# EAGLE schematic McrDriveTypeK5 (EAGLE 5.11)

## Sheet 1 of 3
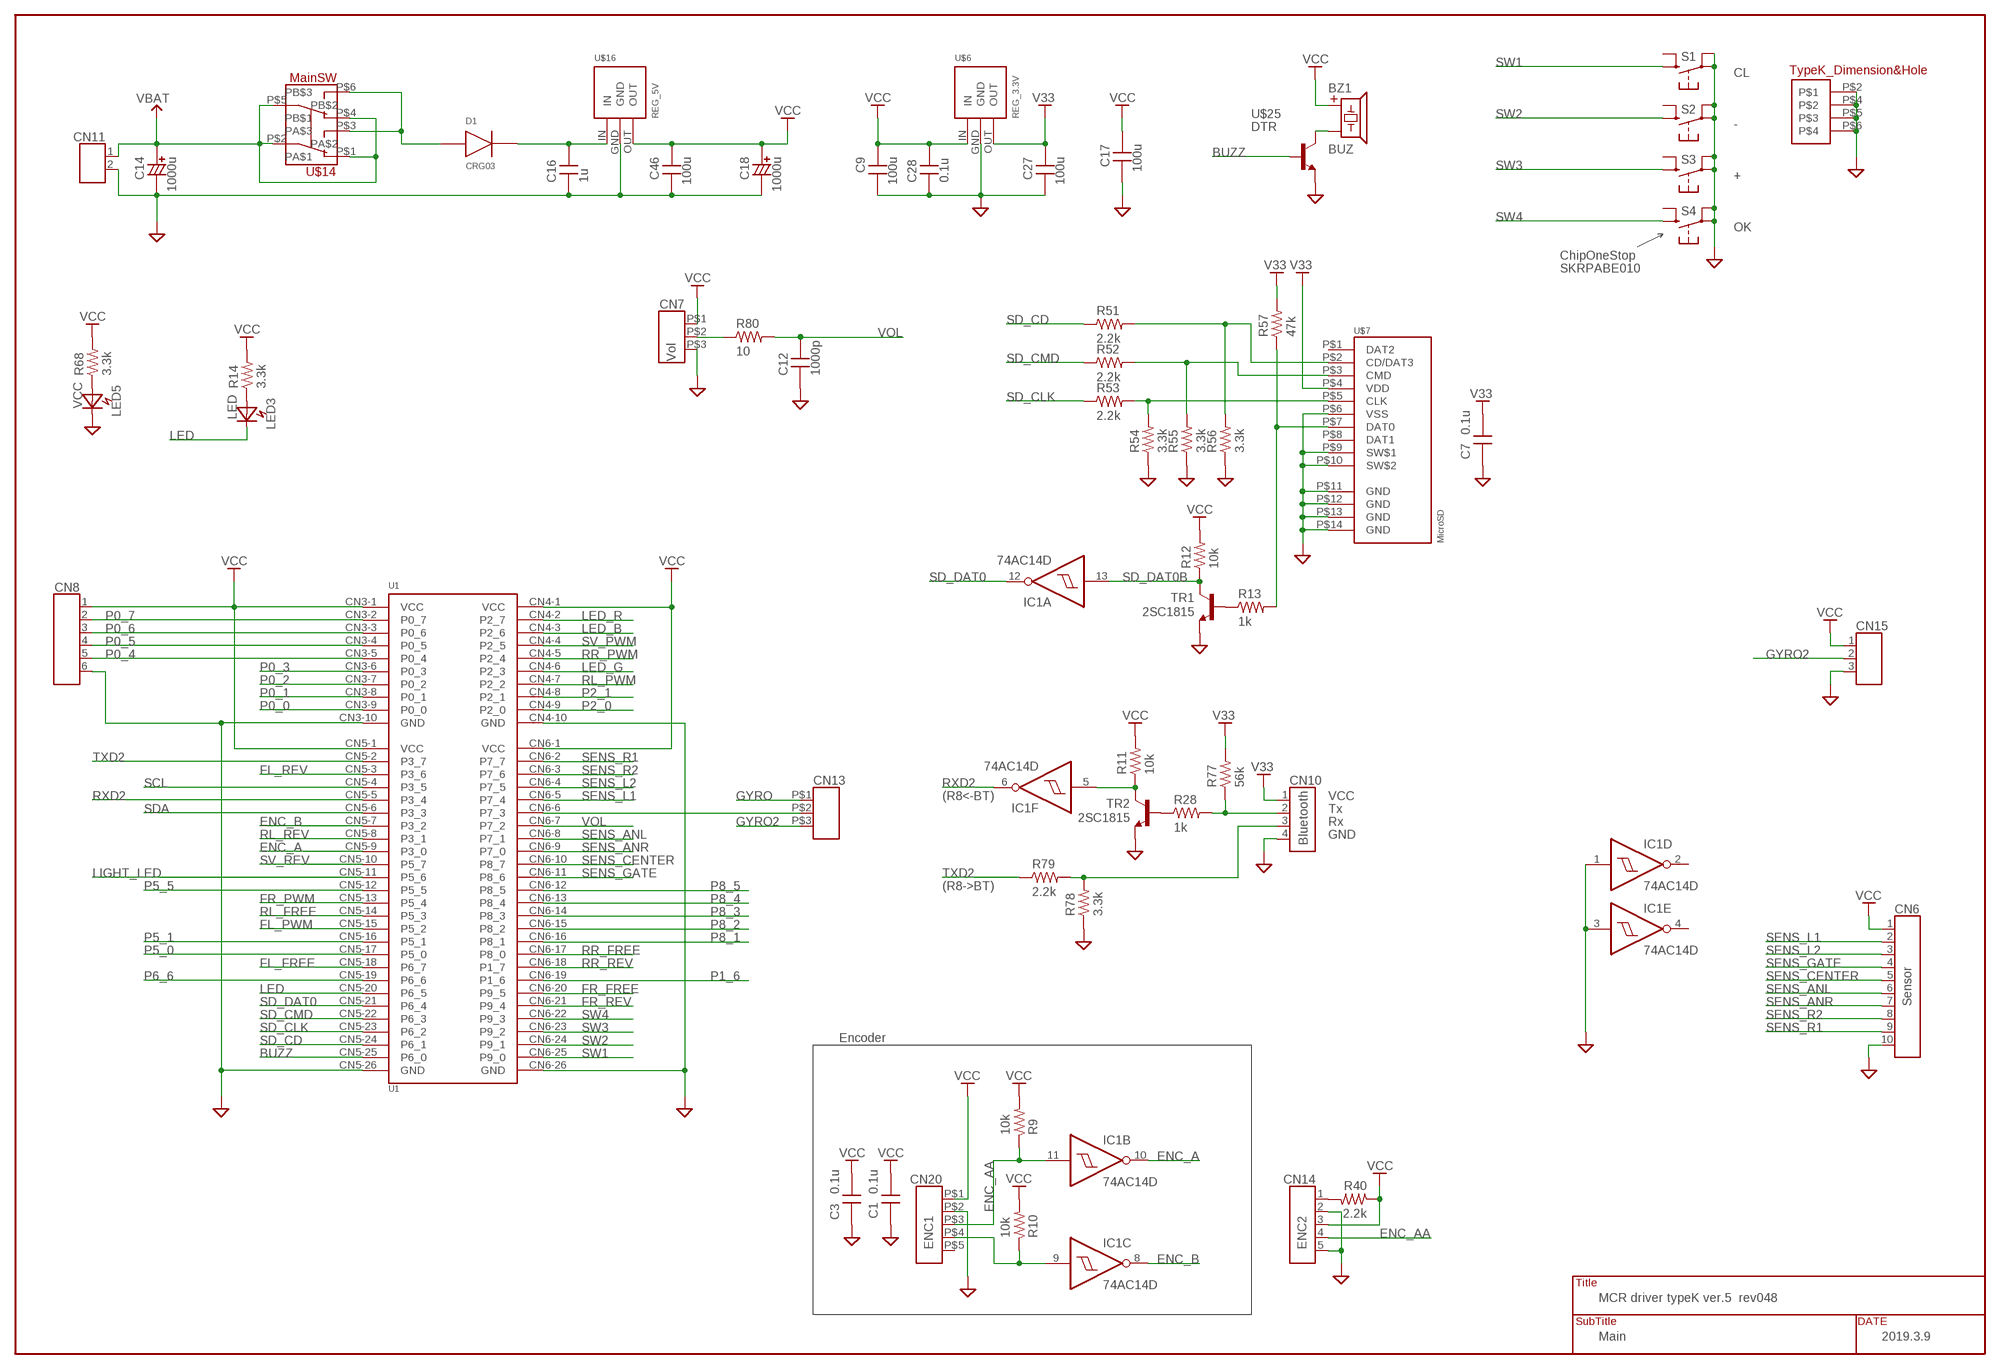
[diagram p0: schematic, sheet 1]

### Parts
BZ1  BUZ  BZ-13  [13B]
C1  0.1u  CAPSM1608C  [C1608C]
C3  0.1u  CAPSM1608C  [C1608C]
C7  0.1u  CAPSM1608C  [C1608C]
C9  100u  CAPSM3216  [C3216]
C12  1000p  CAPSM1608C  [C1608C]
C14  1000u  CCAP10.5  [CCAP_10.5]
C16  1u  CAPSM1608C  [C1608C]
C17  100u  CAPSM3216  [C3216]
C18  1000u  CCAP10.5  [CCAP_10.5]
C27  100u  CAPSM3216  [C3216]
C28  0.1u  CAPSM1608C  [C1608C]
C46  100u  CAPSM3216  [C3216]
CN6  Sensor  CON_10P-1.0  [ML10]
CN7  Vol  CON_3P-XH  [3P-XH]
CN8  CON_6P-1.0B  [6P-S2]
CN10  Bluetooth  CON_4P-1.0-2  [4P-S2]
CN11  CON_2P-VH  [2P-VH]
CN13  CON_3P-SMD  [3P-SMD]
CN14  ENC2  CON_5P-1.0B  [5P-S2]
CN15  CON_3P-1.0-2  [3P-S2]
CN20  ENC1  CON_5P-DF3A  [DF3A-5P]
D1  CRG03  DIODES  [CRG03]
IC1  74AC14D  [SO14]
LED3  LED  LED-1608B  [LED_1608B]
LED5  VCC  LED-1608B  [LED_1608B]
R9  10k  R1608C  [C1608C]
R10  10k  R1608C  [C1608C]
R11  10k  R1608C  [C1608C]
R12  10k  R1608C  [C1608C]
R13  1k  R1608C  [C1608C]
R14  3.3k  R1608C  [C1608C]
R28  1k  R1608C  [C1608C]
R40  2.2k  R1608C  [C1608C]
R51  2.2k  R1608C  [C1608C]
R52  2.2k  R1608C  [C1608C]
R53  2.2k  R1608C  [C1608C]
R54  3.3k  R1608C  [C1608C]
R55  3.3k  R1608C  [C1608C]
R56  3.3k  R1608C  [C1608C]
R57  47k  R1608C  [C1608C]
R68  3.3k  R1608C  [C1608C]
R77  56k  R1608C  [C1608C]
R78  3.3k  R1608C  [C1608C]
R79  2.2k  R1608C  [C1608C]
R80  10  R1608C  [C1608C]
S1  CL  T-SWITCHSKRP  [TSW_SKRP]
S2  -  T-SWITCHSKRP  [TSW_SKRP]
S3  +  T-SWITCHSKRP  [TSW_SKRP]
S4  OK  T-SWITCHSKRP  [TSW_SKRP]
TR1  2SC1815  2SC1815-SC70  [SC70]
TR2  2SC1815  2SC1815-SC70  [SC70]
U1  RY-R8C38  [RY-R8C38]
U$1  TYPE_K5EE  [TYPE_K5E]
U$6  REG_3.3V  REGULATOR-SMD  [NJM2391DL1]
U$7  MicroSD  SD-MICRO  [DM3AT-SF-PEJ]
U$14  MainSW  SW-6P-0.9  [SW-6P-2.5X3.3]
U$16  REG_5V  REGULATOR-SMD  [NJM2391DL1]
U$25  DTR  2SC1815-SC70  [SC70]

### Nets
BUZZ: U1.CN5-25(P6_0) U$25.B
ENC_A: IC1.10(B:O) U1.CN5-9(P3_0)
ENC_AA: CN14.4 CN20.P$3 IC1.11(B:I) R9.1
ENC_B: IC1.8(C:O) U1.CN5-7(P3_2)
FL_FREE: U1.CN5-18(P6_7) ; also sheet 2
FL_PWM: U1.CN5-15(P5_2) ; also sheet 2
FL_REV: U1.CN5-3(P3_6) ; also sheet 2
FR_FREE: U1.CN6-20(P9_5) ; also sheet 2
FR_PWM: U1.CN5-13(P5_4) ; also sheet 2
FR_REV: U1.CN6-21(P9_4) ; also sheet 2
GND: C1.1 C3.1 C7.1 C9.2 C12.1 C14.- C16.1 C17.2 C18.- C27.2 C28.1 C46.2 CN6.10 CN7.P$3 CN8.6 CN10.4 CN11.2 CN14.2 CN14.5 CN15.3 CN20.P$2 IC1.1(D:I) IC1.3(E:I) LED5.K R54.1 R55.1 R56.1 R78.1 S1.P$1(P) S1.P$2(P1) S2.P$1(P) S2.P$2(P1) S3.P$1(P) S3.P$2(P1) S4.P$1(P) S4.P$2(P1) TR1.E TR2.E U1.CN3-10(GND) U1.CN4-10(GND) U1.CN5-26(GND) U1.CN6-26(GND) U$1.P$2 U$1.P$4 U$1.P$5 U$1.P$6 U$6.GND U$7.P$6(VSS) U$7.P$9(SW$1) U$7.P$10(SW$2) U$7.P$11(GND) U$7.P$12(GND) U$7.P$13(GND) U$7.P$14(GND) U$16.GND U$25.E ; also sheet 2,3
GYRO: CN13.P$1 ; also sheet 3
GYRO2: CN13.P$3 CN15.2
LED: LED3.K U1.CN5-20(P6_5)
LED_B: U1.CN4-3(P2_6) ; also sheet 3
LED_G: U1.CN4-6(P2_3) ; also sheet 3
LED_R: U1.CN4-2(P2_7) ; also sheet 3
LIGHT_LED: U1.CN5-11(P5_6)
N$4: CN7.P$2 R80.1
N$7: CN13.P$2 U1.CN6-6(P7_3)
N$14: R13.2 R57.1 U$7.P$7(DAT0)
N$15: R13.1 TR1.B
N$20: LED3.A R14.1
N$46: CN20.P$4 IC1.9(C:I) R10.1
N$62: BZ1.- U$25.C
N$94: C16.2 D1.K U$16.IN
N$95: R53.2 R54.2 U$7.P$5(CLK)
N$96: CN14.1 R40.2
N$97: D1.A U$14.P$3(PA$3) U$14.P$6(PB$3)
N$102: LED5.A R68.1
N$110: IC1.5(F:I) R11.1 TR2.C
N$113: R51.2 R56.2 U$7.P$2(CD/DAT3)
N$114: R52.2 R55.2 U$7.P$3(CMD)
N$130: R28.1 TR2.B
N$131: CN10.2 R28.2 R77.1
N$135: CN10.3 R78.2 R79.2
P0_0: U1.CN3-9(P0_0)
P0_1: U1.CN3-8(P0_1)
P0_2: U1.CN3-7(P0_2)
P0_3: U1.CN3-6(P0_3)
P0_4: CN8.5 U1.CN3-5(P0_4)
P0_5: CN8.4 U1.CN3-4(P0_5)
P0_6: CN8.3 U1.CN3-3(P0_6)
P0_7: CN8.2 U1.CN3-2(P0_7)
P1_6: U1.CN6-19(P1_6)
P2_0: U1.CN4-9(P2_0)
P2_1: U1.CN4-8(P2_1)
P5_0: U1.CN5-17(P5_0)
P5_1: U1.CN5-16(P5_1)
P5_5: U1.CN5-12(P5_5)
P6_6: U1.CN5-19(P6_6)
P8_1: U1.CN6-16(P8_1)
P8_2: U1.CN6-15(P8_2)
P8_3: U1.CN6-14(P8_3)
P8_4: U1.CN6-13(P8_4)
P8_5: U1.CN6-12(P8_5)
RL_FREE: U1.CN5-14(P5_3) ; also sheet 2
RL_PWM: U1.CN4-7(P2_2) ; also sheet 2
RL_REV: U1.CN5-8(P3_1) ; also sheet 2
RR_FREE: U1.CN6-17(P8_0) ; also sheet 2
RR_PWM: U1.CN4-5(P2_4) ; also sheet 2
RR_REV: U1.CN6-18(P1_7) ; also sheet 2
RXD2: IC1.6(F:O) U1.CN5-5(P3_4)
SCL: U1.CN5-4(P3_5) ; also sheet 3
SD_CD: R51.1 U1.CN5-24(P6_1)
SD_CLK: R53.1 U1.CN5-23(P6_2)
SD_CMD: R52.1 U1.CN5-22(P6_3)
SD_DAT0: IC1.12(A:O) U1.CN5-21(P6_4)
SD_DAT0B: IC1.13(A:I) R12.1 TR1.C
SDA: U1.CN5-6(P3_3) ; also sheet 3
SENS_ANL: CN6.6 U1.CN6-8(P7_1)
SENS_ANR: CN6.7 U1.CN6-9(P7_0)
SENS_CENTER: CN6.5 U1.CN6-10(P8_7)
SENS_GATE: CN6.4 U1.CN6-11(P8_6)
SENS_L1: CN6.2 U1.CN6-5(P7_4)
SENS_L2: CN6.3 U1.CN6-4(P7_5)
SENS_R1: CN6.9 U1.CN6-2(P7_7)
SENS_R2: CN6.8 U1.CN6-3(P7_6)
SV_PWM: U1.CN4-4(P2_5) ; also sheet 2
SV_REV: U1.CN5-10(P5_7) ; also sheet 2
SW1: S1.P$3(S) U1.CN6-25(P9_0)
SW2: S2.P$3(S) U1.CN6-24(P9_1)
SW3: S3.P$3(S) U1.CN6-23(P9_2)
SW4: S4.P$3(S) U1.CN6-22(P9_3)
TXD2: R79.1 U1.CN5-2(P3_7)
V33: C7.2 C27.1 CN10.1 R57.2 R77.2 U$6.OUT U$7.P$4(VDD) ; also sheet 3
VBAT: C14.+ CN11.1 U$14.P$1(PA$1) U$14.P$2(PA$2) U$14.P$4(PB$1) U$14.P$5(PB$2) ; also sheet 2
VCC: BZ1.+ C1.2 C3.2 C9.1 C17.1 C18.+ C28.2 C46.1 CN6.1 CN7.P$1 CN8.1 CN14.3 CN15.1 CN20.P$1 R9.2 R10.2 R11.2 R12.2 R14.2 R40.1 R68.2 U1.CN3-1(VCC) U1.CN4-1(VCC) U1.CN5-1(VCC) U1.CN6-1(VCC) U$6.IN U$16.OUT ; also sheet 2,3
VOL: C12.2 R80.2 U1.CN6-7(P7_2)
Unconnected: CN20.P$5 IC1.2(D:O) IC1.4(E:O) S1.P$4(S1) S2.P$4(S1) S3.P$4(S1) S4.P$4(S1) U$7.P$1(DAT2) U$7.P$8(DAT1)

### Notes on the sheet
- ChipOneStop
- SKRPABE010
- (R8<-BT) | VCC
- Tx
- Rx
- GND
- (R8->BT)
- Encoder
- MCR driver typeK ver.5  rev048
- Main | 2019.3.9

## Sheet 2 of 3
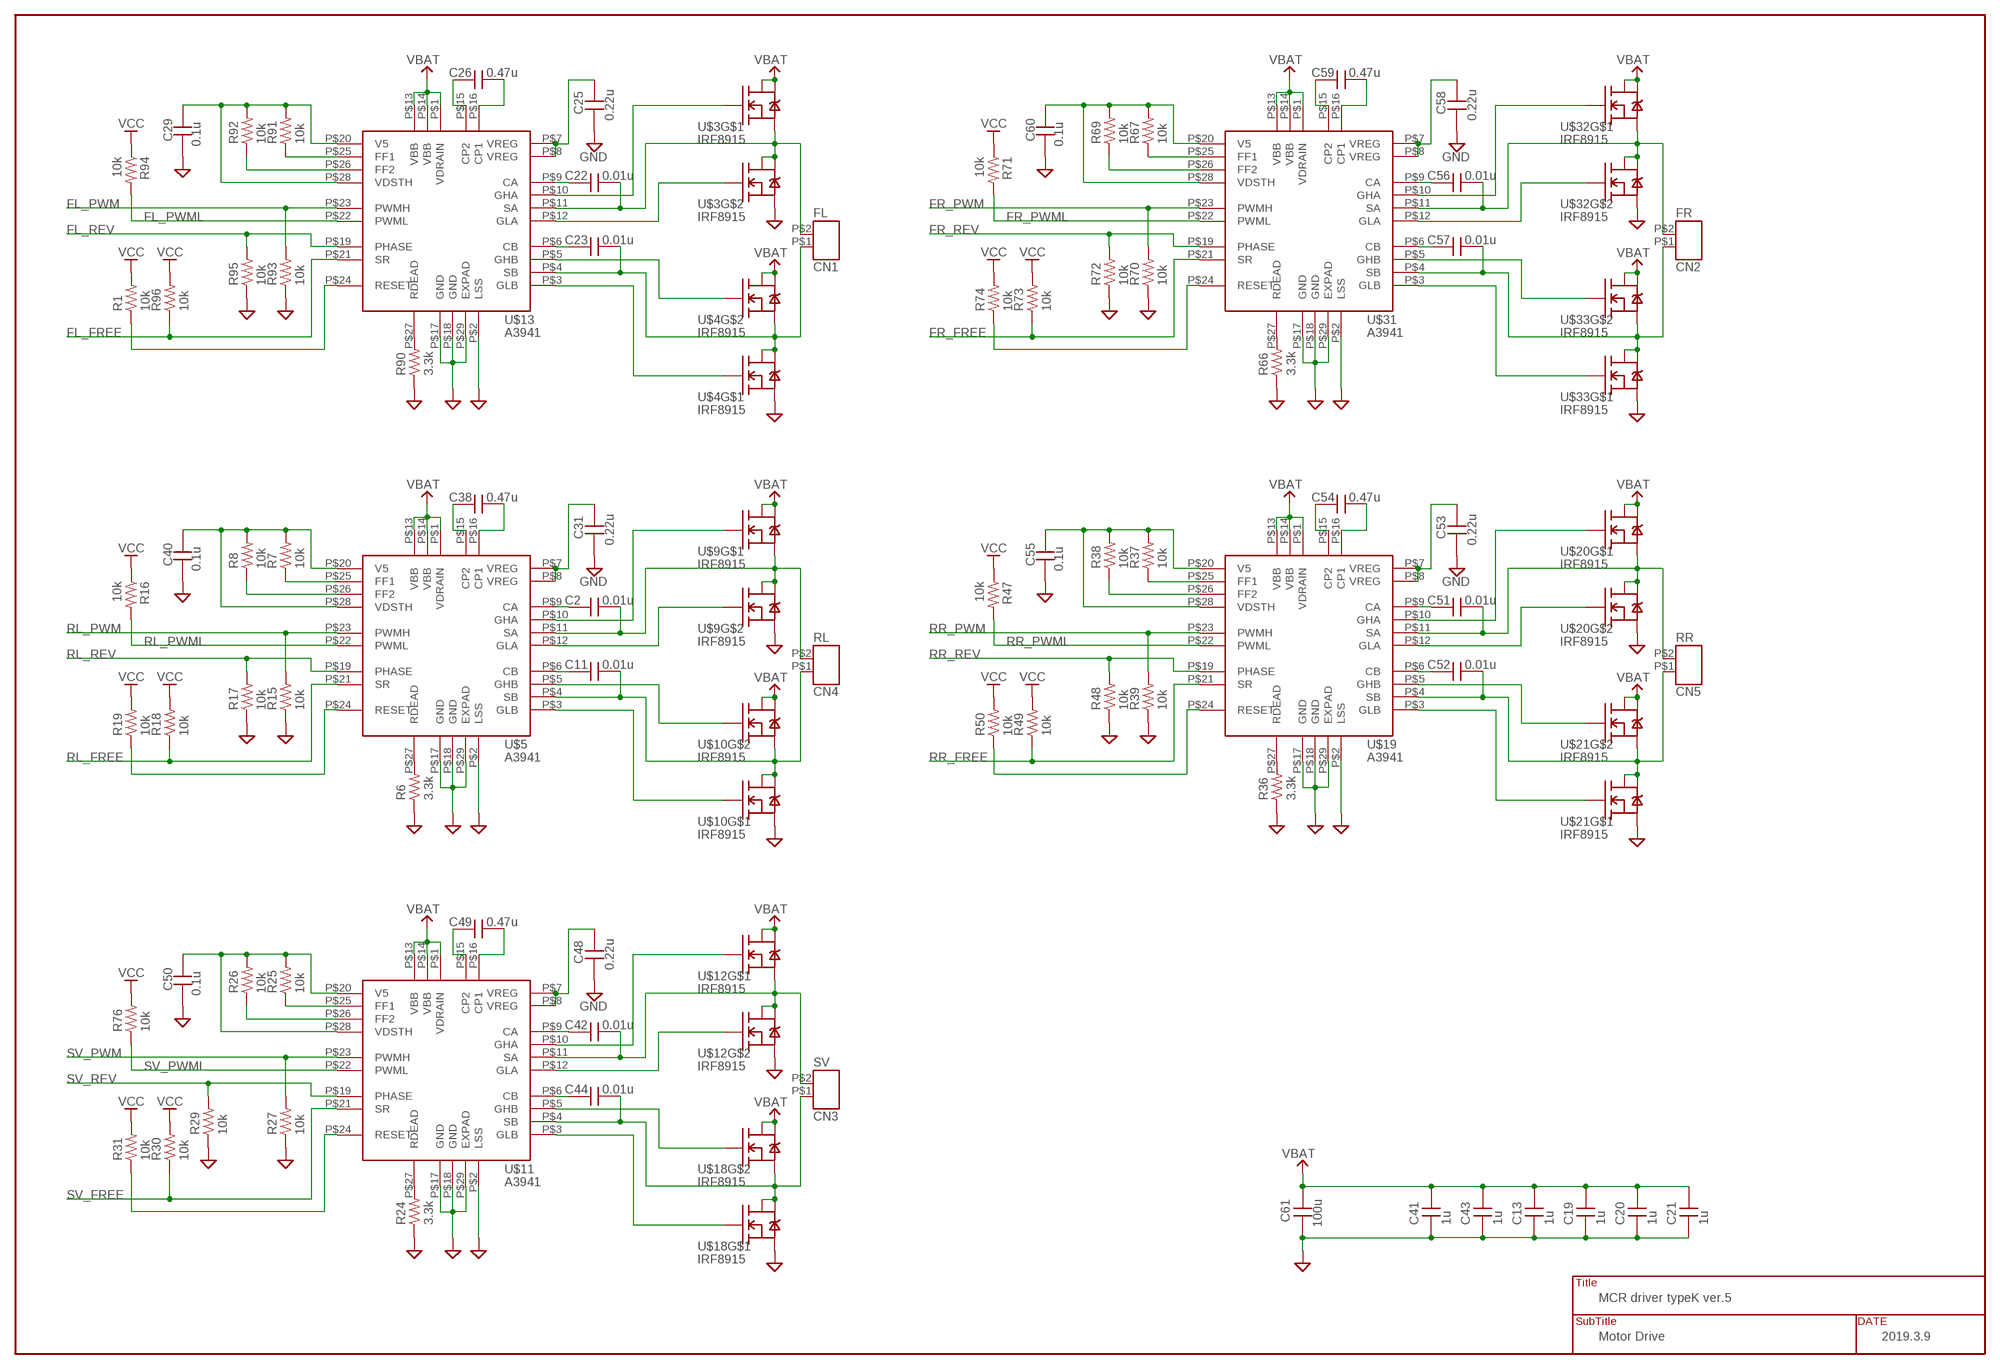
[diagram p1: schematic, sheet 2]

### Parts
C2  0.01u  CAPSM1608C  [C1608C]
C11  0.01u  CAPSM1608C  [C1608C]
C13  1u  CAPSM1608C  [C1608C]
C19  1u  CAPSM1608C  [C1608C]
C20  1u  CAPSM1608C  [C1608C]
C21  1u  CAPSM1608C  [C1608C]
C22  0.01u  CAPSM1608C  [C1608C]
C23  0.01u  CAPSM1608C  [C1608C]
C25  0.22u  CAPSM1608C  [C1608C]
C26  0.47u  CAPSM1608C  [C1608C]
C29  0.1u  CAPSM1608C  [C1608C]
C31  0.22u  CAPSM1608C  [C1608C]
C38  0.47u  CAPSM1608C  [C1608C]
C40  0.1u  CAPSM1608C  [C1608C]
C41  1u  CAPSM1608C  [C1608C]
C42  0.01u  CAPSM1608C  [C1608C]
C43  1u  CAPSM1608C  [C1608C]
C44  0.01u  CAPSM1608C  [C1608C]
C48  0.22u  CAPSM1608C  [C1608C]
C49  0.47u  CAPSM1608C  [C1608C]
C50  0.1u  CAPSM1608C  [C1608C]
C51  0.01u  CAPSM1608C  [C1608C]
C52  0.01u  CAPSM1608C  [C1608C]
C53  0.22u  CAPSM1608C  [C1608C]
C54  0.47u  CAPSM1608C  [C1608C]
C55  0.1u  CAPSM1608C  [C1608C]
C56  0.01u  CAPSM1608C  [C1608C]
C57  0.01u  CAPSM1608C  [C1608C]
C58  0.22u  CAPSM1608C  [C1608C]
C59  0.47u  CAPSM1608C  [C1608C]
C60  0.1u  CAPSM1608C  [C1608C]
C61  100u  CAPSM3216  [C3216]
CN1  FL  CON_2P-XH  [2P-XH]
CN2  FR  CON_2P-XH  [2P-XH]
CN3  SV  CON_2P-XH  [2P-XH]
CN4  RL  CON_2P-XH  [2P-XH]
CN5  RR  CON_2P-XH  [2P-XH]
R1  10k  R1608C  [C1608C]
R6  3.3k  R1608C  [C1608C]
R7  10k  R1608C  [C1608C]
R8  10k  R1608C  [C1608C]
R15  10k  R1608C  [C1608C]
R16  10k  R1608C  [C1608C]
R17  10k  R1608C  [C1608C]
R18  10k  R1608C  [C1608C]
R19  10k  R1608C  [C1608C]
R24  3.3k  R1608C  [C1608C]
R25  10k  R1608C  [C1608C]
R26  10k  R1608C  [C1608C]
R27  10k  R1608C  [C1608C]
R29  10k  R1608C  [C1608C]
R30  10k  R1608C  [C1608C]
R31  10k  R1608C  [C1608C]
R36  3.3k  R1608C  [C1608C]
R37  10k  R1608C  [C1608C]
R38  10k  R1608C  [C1608C]
R39  10k  R1608C  [C1608C]
R47  10k  R1608C  [C1608C]
R48  10k  R1608C  [C1608C]
R49  10k  R1608C  [C1608C]
R50  10k  R1608C  [C1608C]
R66  3.3k  R1608C  [C1608C]
R67  10k  R1608C  [C1608C]
R69  10k  R1608C  [C1608C]
R70  10k  R1608C  [C1608C]
R71  10k  R1608C  [C1608C]
R72  10k  R1608C  [C1608C]
R73  10k  R1608C  [C1608C]
R74  10k  R1608C  [C1608C]
R76  10k  R1608C  [C1608C]
R90  3.3k  R1608C  [C1608C]
R91  10k  R1608C  [C1608C]
R92  10k  R1608C  [C1608C]
R93  10k  R1608C  [C1608C]
R94  10k  R1608C  [C1608C]
R95  10k  R1608C  [C1608C]
R96  10k  R1608C  [C1608C]
U$3  IRF8915  IRF8915SOIC  [8SOIC]
U$4  IRF8915  IRF8915SOIC  [8SOIC]
U$5  A3941  A3941TSSOP  [A3941]
U$9  IRF8915  IRF8915SOIC  [8SOIC]
U$10  IRF8915  IRF8915SOIC  [8SOIC]
U$11  A3941  A3941TSSOP  [A3941]
U$12  IRF8915  IRF8915SOIC  [8SOIC]
U$13  A3941  A3941TSSOP  [A3941]
U$18  IRF8915  IRF8915SOIC  [8SOIC]
U$19  A3941  A3941TSSOP  [A3941]
U$20  IRF8915  IRF8915SOIC  [8SOIC]
U$21  IRF8915  IRF8915SOIC  [8SOIC]
U$31  A3941  A3941TSSOP  [A3941]
U$32  IRF8915  IRF8915SOIC  [8SOIC]
U$33  IRF8915  IRF8915SOIC  [8SOIC]

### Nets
FL_FREE: R96.1 U$13.P$21(SR) ; also sheet 1
FL_PWM: R93.2 U$13.P$23(PWMH) ; also sheet 1
FL_PWML: R94.2 U$13.P$22(PWML)
FL_REV: R95.2 U$13.P$19(PHASE) ; also sheet 1
FR_FREE: R73.1 U$31.P$21(SR) ; also sheet 1
FR_PWM: R70.2 U$31.P$23(PWMH) ; also sheet 1
FR_PWML: R71.2 U$31.P$22(PWML)
FR_REV: R72.2 U$31.P$19(PHASE) ; also sheet 1
GND: C13.1 C19.1 C20.1 C21.1 C25.2 C29.1 C31.2 C40.1 C41.1 C43.1 C48.2 C50.1 C53.2 C55.1 C58.2 C60.1 C61.2 R6.1 R15.1 R17.1 R24.1 R27.1 R29.1 R36.1 R39.1 R48.1 R66.1 R70.1 R72.1 R90.1 R93.1 R95.1 U$3.P$3(S) U$4.P$1(S) U$5.P$2(LSS) U$5.P$17(GND) U$5.P$18(GND) U$5.P$29(EXPAD) U$9.P$3(S) U$10.P$1(S) U$11.P$2(LSS) U$11.P$17(GND) U$11.P$18(GND) U$11.P$29(EXPAD) U$12.P$3(S) U$13.P$2(LSS) U$13.P$17(GND) U$13.P$18(GND) U$13.P$29(EXPAD) U$18.P$1(S) U$19.P$2(LSS) U$19.P$17(GND) U$19.P$18(GND) U$19.P$29(EXPAD) U$20.P$3(S) U$21.P$1(S) U$31.P$2(LSS) U$31.P$17(GND) U$31.P$18(GND) U$31.P$29(EXPAD) U$32.P$3(S) U$33.P$1(S) ; also sheet 1,3
N$1: C2.2 CN4.P$2 U$5.P$11(SA) U$9.P$1(S) U$9.P$5(D) U$9.P$6(D)
N$2: R1.1 U$13.P$24(RESET)
N$3: C26.1 U$13.P$15(CP2)
N$6: C29.2 R91.2 R92.2 U$13.P$20(V5) U$13.P$28(VDSTH)
N$8: C11.2 CN4.P$1 U$5.P$4(SB) U$10.P$3(S) U$10.P$7(D) U$10.P$8(D)
N$9: U$5.P$10(GHA) U$9.P$2(G)
N$11: R91.1 U$13.P$25(FF1)
N$16: U$5.P$12(GLA) U$9.P$4(G)
N$17: U$5.P$5(GHB) U$10.P$4(G)
N$18: U$5.P$3(GLB) U$10.P$2(G)
N$19: C2.1 U$5.P$9(CA)
N$21: C22.2 CN1.P$2 U$3.P$1(S) U$3.P$5(D) U$3.P$6(D) U$13.P$11(SA)
N$22: C11.1 U$5.P$6(CB)
N$23: R6.2 U$5.P$27(RDEAD)
N$24: C31.1 U$5.P$7(VREG) U$5.P$8(VREG)
N$25: C38.2 U$5.P$16(CP1)
N$26: C22.1 U$13.P$9(CA)
N$27: C23.2 CN1.P$1 U$4.P$3(S) U$4.P$7(D) U$4.P$8(D) U$13.P$4(SB)
N$28: R8.1 U$5.P$26(FF2)
N$29: R19.1 U$5.P$24(RESET)
N$31: C38.1 U$5.P$15(CP2)
N$32: C40.2 R7.2 R8.2 U$5.P$20(V5) U$5.P$28(VDSTH)
N$33: R7.1 U$5.P$25(FF1)
N$37: C23.1 U$13.P$6(CB)
N$39: C42.2 CN3.P$2 U$11.P$11(SA) U$12.P$1(S) U$12.P$5(D) U$12.P$6(D)
N$40: C44.2 CN3.P$1 U$11.P$4(SB) U$18.P$3(S) U$18.P$7(D) U$18.P$8(D)
N$41: U$11.P$10(GHA) U$12.P$2(G)
N$42: U$11.P$12(GLA) U$12.P$4(G)
N$43: U$11.P$5(GHB) U$18.P$4(G)
N$44: U$11.P$3(GLB) U$18.P$2(G)
N$47: C42.1 U$11.P$9(CA)
N$48: C44.1 U$11.P$6(CB)
N$49: R24.2 U$11.P$27(RDEAD)
N$50: C48.1 U$11.P$7(VREG) U$11.P$8(VREG)
N$51: C49.2 U$11.P$16(CP1)
N$52: R26.1 U$11.P$26(FF2)
N$53: R31.1 U$11.P$24(RESET)
N$54: C49.1 U$11.P$15(CP2)
N$55: C50.2 R25.2 R26.2 U$11.P$20(V5) U$11.P$28(VDSTH)
N$56: R25.1 U$11.P$25(FF1)
N$57: U$3.P$2(G) U$13.P$10(GHA)
N$58: U$3.P$4(G) U$13.P$12(GLA)
N$61: U$4.P$4(G) U$13.P$5(GHB)
N$65: U$4.P$2(G) U$13.P$3(GLB)
N$66: R90.2 U$13.P$27(RDEAD)
N$67: R92.1 U$13.P$26(FF2)
N$70: C51.2 CN5.P$2 U$19.P$11(SA) U$20.P$1(S) U$20.P$5(D) U$20.P$6(D)
N$71: C52.2 CN5.P$1 U$19.P$4(SB) U$21.P$3(S) U$21.P$7(D) U$21.P$8(D)
N$72: U$19.P$10(GHA) U$20.P$2(G)
N$73: U$19.P$12(GLA) U$20.P$4(G)
N$74: U$19.P$5(GHB) U$21.P$4(G)
N$75: C25.1 U$13.P$7(VREG) U$13.P$8(VREG)
N$76: U$19.P$3(GLB) U$21.P$2(G)
N$77: C51.1 U$19.P$9(CA)
N$78: C52.1 U$19.P$6(CB)
N$79: R36.2 U$19.P$27(RDEAD)
N$80: C53.1 U$19.P$7(VREG) U$19.P$8(VREG)
N$81: C26.2 U$13.P$16(CP1)
N$82: C54.2 U$19.P$16(CP1)
N$83: R38.1 U$19.P$26(FF2)
N$84: R50.1 U$19.P$24(RESET)
N$85: C54.1 U$19.P$15(CP2)
N$86: C55.2 R37.2 R38.2 U$19.P$20(V5) U$19.P$28(VDSTH)
N$88: R37.1 U$19.P$25(FF1)
N$93: C56.2 CN2.P$2 U$31.P$11(SA) U$32.P$1(S) U$32.P$5(D) U$32.P$6(D)
N$103: C57.2 CN2.P$1 U$31.P$4(SB) U$33.P$3(S) U$33.P$7(D) U$33.P$8(D)
N$104: U$31.P$10(GHA) U$32.P$2(G)
N$105: U$31.P$12(GLA) U$32.P$4(G)
N$106: U$31.P$5(GHB) U$33.P$4(G)
N$107: U$31.P$3(GLB) U$33.P$2(G)
N$108: C56.1 U$31.P$9(CA)
N$109: C57.1 U$31.P$6(CB)
N$111: R66.2 U$31.P$27(RDEAD)
N$112: C58.1 U$31.P$7(VREG) U$31.P$8(VREG)
N$115: C59.2 U$31.P$16(CP1)
N$116: R69.1 U$31.P$26(FF2)
N$117: R74.1 U$31.P$24(RESET)
N$118: C59.1 U$31.P$15(CP2)
N$122: C60.2 R67.2 R69.2 U$31.P$20(V5) U$31.P$28(VDSTH)
N$124: R67.1 U$31.P$25(FF1)
RL_FREE: R18.1 U$5.P$21(SR) ; also sheet 1
RL_PWM: R15.2 U$5.P$23(PWMH) ; also sheet 1
RL_PWML: R16.2 U$5.P$22(PWML)
RL_REV: R17.2 U$5.P$19(PHASE) ; also sheet 1
RR_FREE: R49.1 U$19.P$21(SR) ; also sheet 1
RR_PWM: R39.2 U$19.P$23(PWMH) ; also sheet 1
RR_PWML: R47.2 U$19.P$22(PWML)
RR_REV: R48.2 U$19.P$19(PHASE) ; also sheet 1
SV_FREE: R30.1 U$11.P$21(SR)
SV_PWM: R27.2 U$11.P$23(PWMH) ; also sheet 1
SV_PWML: R76.1 U$11.P$22(PWML)
SV_REV: R29.2 U$11.P$19(PHASE) ; also sheet 1
VBAT: C13.2 C19.2 C20.2 C21.2 C41.2 C43.2 C61.1 U$3.P$7(D) U$3.P$8(D) U$4.P$5(D) U$4.P$6(D) U$5.P$1(VDRAIN) U$5.P$13(VBB) U$5.P$14(VBB) U$9.P$7(D) U$9.P$8(D) U$10.P$5(D) U$10.P$6(D) U$11.P$1(VDRAIN) U$11.P$13(VBB) U$11.P$14(VBB) U$12.P$7(D) U$12.P$8(D) U$13.P$1(VDRAIN) U$13.P$13(VBB) U$13.P$14(VBB) U$18.P$5(D) U$18.P$6(D) U$19.P$1(VDRAIN) U$19.P$13(VBB) U$19.P$14(VBB) U$20.P$7(D) U$20.P$8(D) U$21.P$5(D) U$21.P$6(D) U$31.P$1(VDRAIN) U$31.P$13(VBB) U$31.P$14(VBB) U$32.P$7(D) U$32.P$8(D) U$33.P$5(D) U$33.P$6(D) ; also sheet 1
VCC: R1.2 R16.1 R18.2 R19.2 R30.2 R31.2 R47.1 R49.2 R50.2 R71.1 R73.2 R74.2 R76.2 R94.1 R96.2 ; also sheet 1,3

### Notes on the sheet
- MCR driver typeK ver.5
- Motor Drive | 2019.3.9

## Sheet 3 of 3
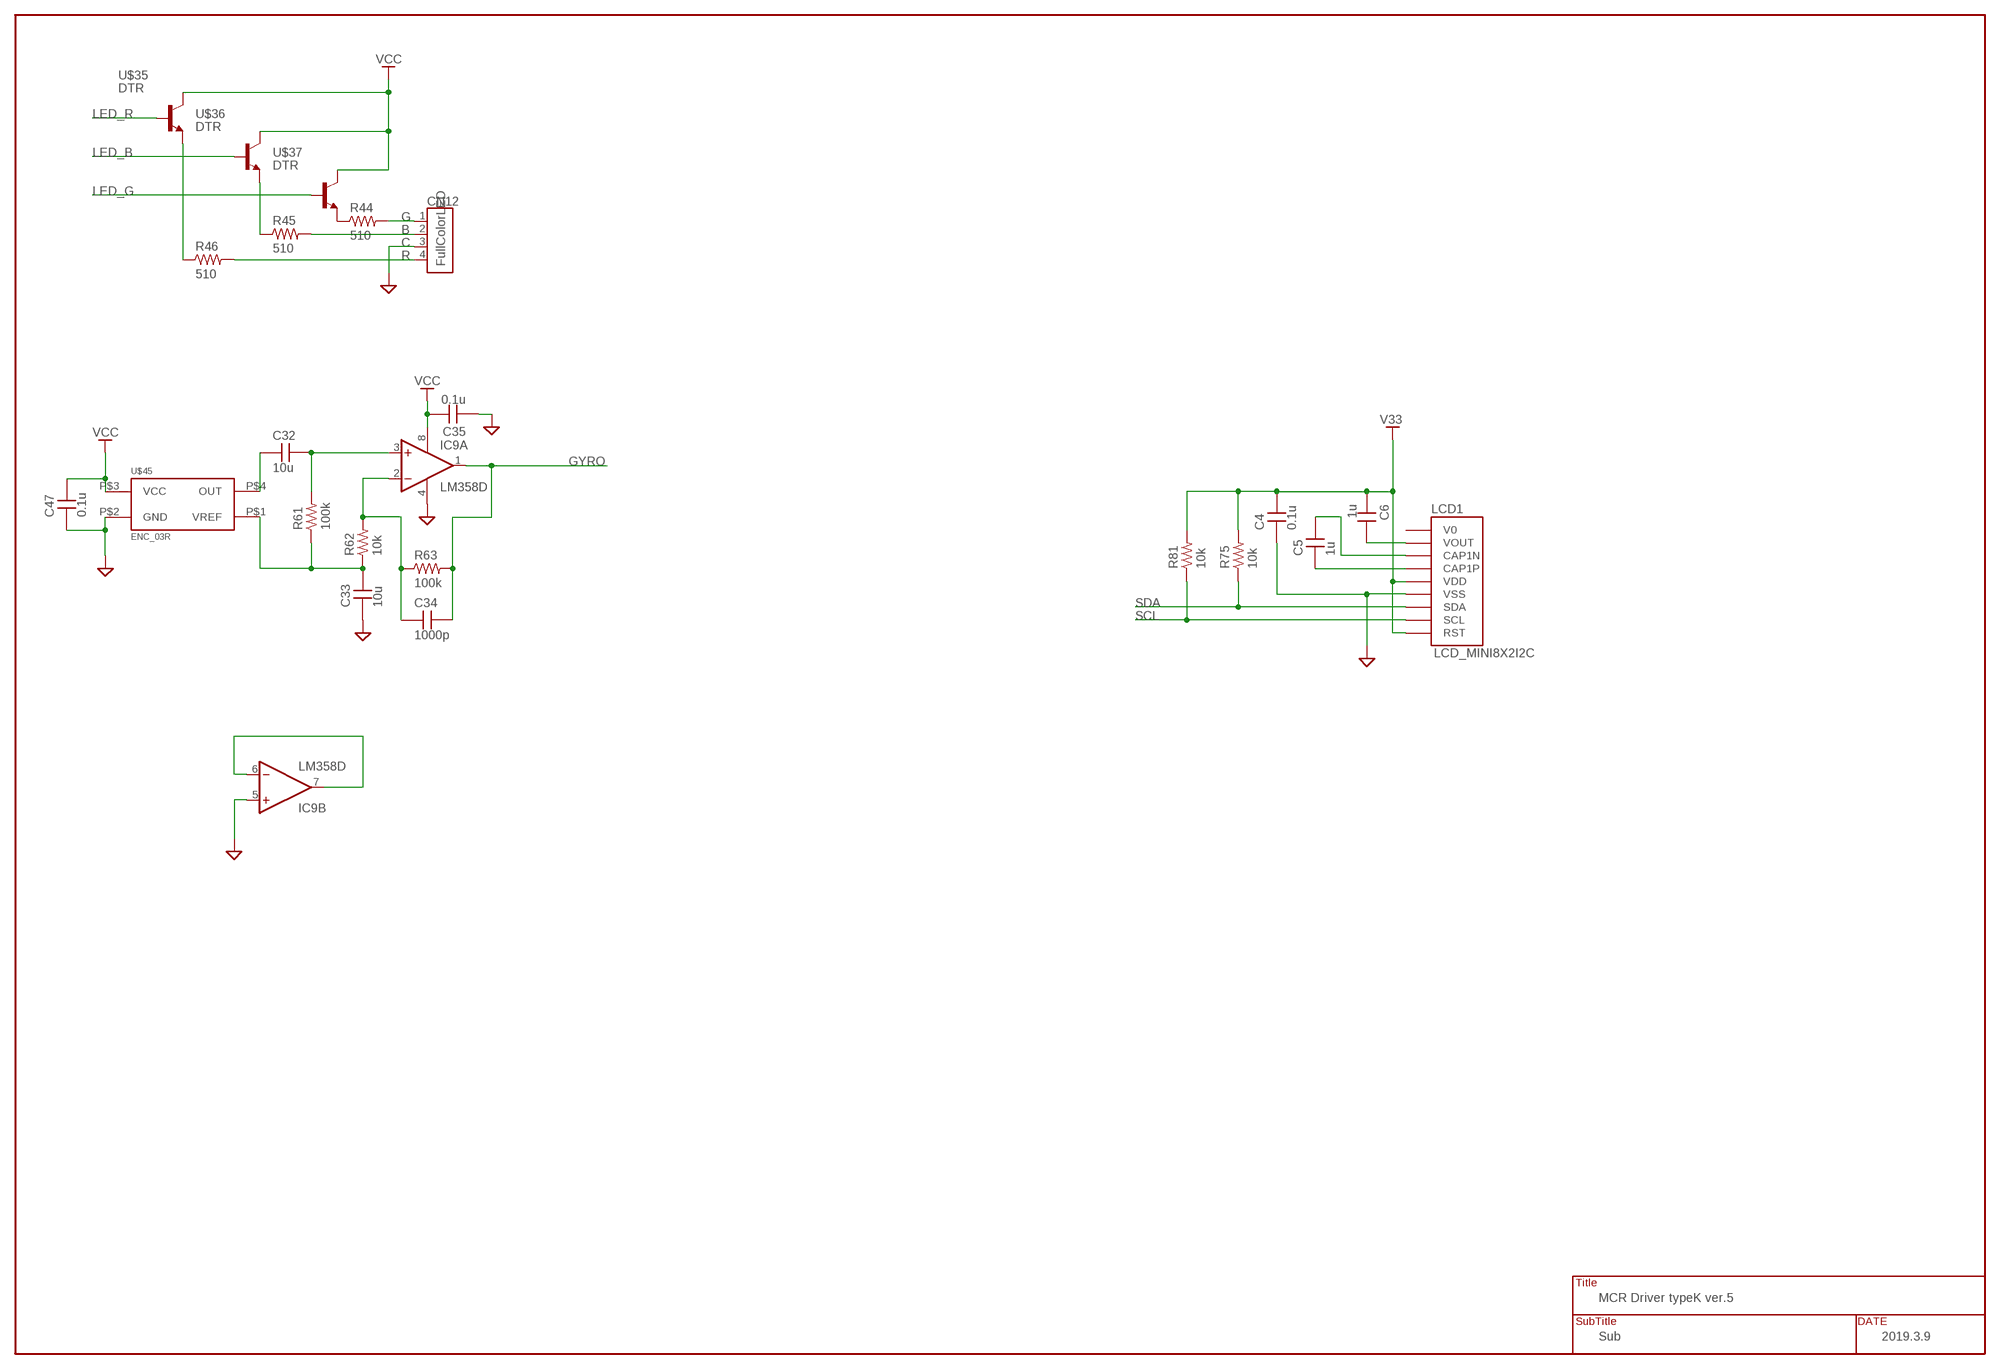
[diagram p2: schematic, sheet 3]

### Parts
C4  0.1u  CAPSM1608C  [C1608C]
C5  1u  CAPSM1608C  [C1608C]
C6  1u  CAPSM1608C  [C1608C]
C32  10u  CAPSM1608C  [C1608C]
C33  10u  CAPSM1608C  [C1608C]
C34  1000p  CAPSM1608C  [C1608C]
C35  0.1u  CAPSM1608C  [C1608C]
C47  0.1u  CAPSM1608C  [C1608C]
CN12  FullColorLED  CON_4P-1.0-2  [4P-S2]
IC9  LM358D  [SO08]
LCD1  LCD_MINI8X2I2C  [LCD_MINI8X2]
R44  510  R1608C  [C1608C]
R45  510  R1608C  [C1608C]
R46  510  R1608C  [C1608C]
R61  100k  R1608C  [C1608C]
R62  10k  R1608C  [C1608C]
R63  100k  R1608C  [C1608C]
R75  10k  R1608C  [C1608C]
R81  10k  R1608C  [C1608C]
U$35  DTR  2SC1815-SC70  [SC70]
U$36  DTR  2SC1815-SC70  [SC70]
U$37  DTR  2SC1815-SC70  [SC70]
U$45  ENC_03R  [ENC_03R]

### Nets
GND: C4.1 C33.1 C35.1 C47.1 CN12.3 IC9.4(P:V-) IC9.5(B:+IN) LCD1.P$6(VSS) U$45.P$2(GND) ; also sheet 1,2
GYRO: C34.2 IC9.1(A:OUT) R63.2 ; also sheet 1
LED_B: U$36.B ; also sheet 1
LED_G: U$37.B ; also sheet 1
LED_R: U$35.B ; also sheet 1
N$30: IC9.6(B:-IN) IC9.7(B:OUT)
N$68: R44.1 U$37.E
N$69: R45.1 U$36.E
N$87: R46.1 U$35.E
N$99: CN12.1 R44.2
N$100: CN12.2 R45.2
N$101: CN12.4 R46.2
N$119: C32.1 U$45.P$4(OUT)
N$120: C32.2 IC9.3(A:+IN) R61.2
N$121: C33.2 R61.1 R62.1 U$45.P$1(VREF)
N$123: C34.1 IC9.2(A:-IN) R62.2 R63.1
N$129: C6.2 LCD1.P$2(VOUT)
N$133: C5.2 LCD1.P$3(CAP1N)
N$134: C5.1 LCD1.P$4(CAP1P)
SCL: LCD1.P$8(SCL) R81.1 ; also sheet 1
SDA: LCD1.P$7(SDA) R75.1 ; also sheet 1
V33: C4.2 C6.1 LCD1.P$5(VDD) LCD1.P$9(RST) R75.2 R81.2 ; also sheet 1
VCC: C35.2 C47.2 IC9.8(P:V+) U$35.C U$36.C U$37.C U$45.P$3(VCC) ; also sheet 1,2
Unconnected: LCD1.P$1(V0)

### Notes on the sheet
- G
- B
- C
- R
- MCR Driver typeK ver.5
- Sub | 2019.3.9

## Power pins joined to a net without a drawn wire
GND: IC1.7(P:GND)
VCC: IC1.14(P:VCC)

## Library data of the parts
BZ1 = _mylib02:BZ: BUZZER
C1-C7 C9 C11-C13 C16 C17 C19-C23 C25-C29 C31-C35 C38 C40-C44 C46-C61 = _mylib02:CAP: Non polar capacitor
C14 C18 = _mylib02:CCAP: Polar capacitor
CN1-CN5 CN11 = _mylib02:CON_2P: 2P Molex Connector
CN6 = _mylib02:CON_10P: 10P Molex Connector
CN7 CN13 CN15 = _mylib02:CON_3P: 3P Molex Connector
CN8 = _mylib02:CON_6P: 6P Molex Connector
CN10 CN12 = _mylib02:CON_4P: 4P Molex Connector
CN14 CN20 = _mylib02:CON_5P: 5P Molex Connector
D1 = _mylib02:DIODE
IC1 = _mylib02:74*14: Hex schmitt trigger INVERTER
IC9 = _mylib02:LM358: OP AMP
LCD1 = _mylib02:LCD_MINI8X2
LED3 LED5 = _mylib02:LED: 3mm LED
R1 R6-R19 R24-R31 R36-R40 R44-R57 R61-R63 R66-R81 R90-R96 = _mylib02:R: General Resiter 1/8W 1/4W 1/2W V/H
S1-S4 = _mylib02:T-SWITCH: TACTILE SWITCH
TR1 TR2 U$25 U$35-U$37 = _mylib02:2SC1815: General use NPN transistor
U1 = _mylib02:RY-R8C38
U$1 = _mylib02:TYPE_K5E
U$3 U$4 U$9 U$10 U$12 U$18 U$20 U$21 U$32 U$33 = _mylib02:IRF8915
U$5 U$11 U$13 U$19 U$31 = _mylib02:A3941
U$6 U$16 = _mylib02:REGULATOR
U$7 = _mylib02:SD-MICRO: Hirose's microSD Card Slot DM3AT-SF-PEJ
U$14 = _mylib02:SW-6P
U$45 = _mylib02:ENC_03R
